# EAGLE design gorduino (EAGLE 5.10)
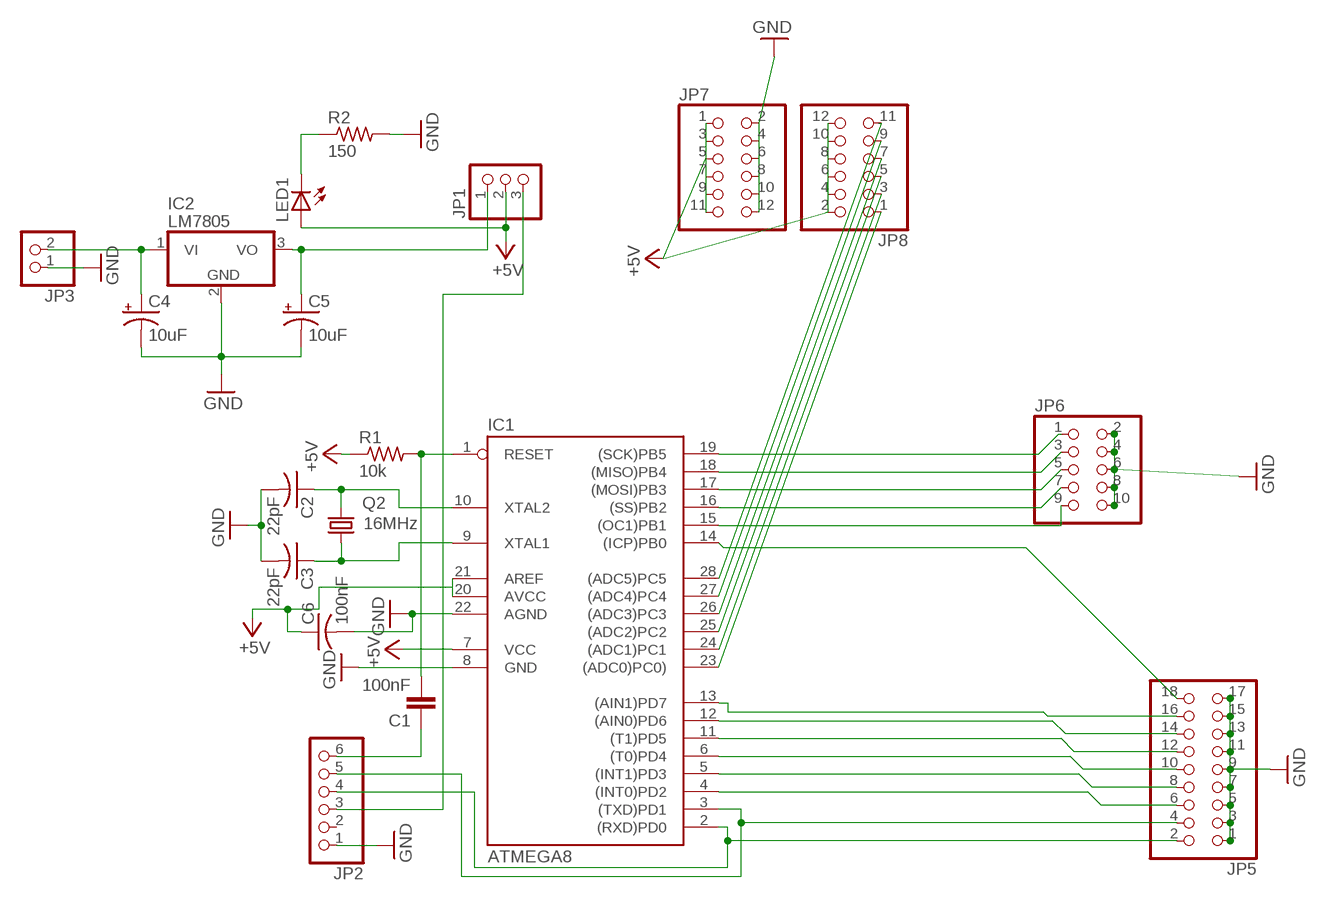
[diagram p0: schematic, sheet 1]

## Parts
C1  100nF  C2.5/2  [C2.5-2]
C2  22pF  C-US025-024X044  [C025-024X044]
C3  22pF  C-US025-024X044  [C025-024X044]
C4  10uF  CPOL-USE2.5-5  [E2,5-5]
C5  10uF  CPOL-USE2.5-5  [E2,5-5]
C6  100nF  C-US025-025X050  [C025-025X050]
IC1  ATMEGA8  AT90S4433P  [DIL28-3]
IC2  LM7805  7805TV  [TO220V]
JP1  PINHD-1X3  [1X03]
JP2  PINHD-1X6  [1X06]
JP3  PINHD-1X2  [1X02]
JP5  PINHD-2X9  [2X09]
JP6  PINHD-2X5  [2X05]
JP7  PINHD-2X6  [2X06]
JP8  PINHD-2X6  [2X06]
LED1  LED3MM  [LED3MM]
Q2  16MHz  CRYTALHC49S  [HC49/S]
R1  10k  R-US_0207/10  [0207/10]
R2  150  R-US_0207/10  [0207/10]

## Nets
+5V [usbvcc]: C6.1 IC1.7(VCC) IC1.20(AVCC) IC1.21(AREF) JP1.2 JP7.1 JP7.3 JP7.5 JP7.7 JP7.9 JP7.11 JP8.2 JP8.4 JP8.6 JP8.8 JP8.10 JP8.12 LED1.A R1.1
N$1: C4.+ IC2.1(VI) JP3.2
N$2 [usbvcc]: C5.+ IC2.3(VO) JP1.1
N$3: LED1.K(C) R2.1
N$4: C1.1 JP2.6
N$5: IC1.2((RXD)PD0) JP2.4 JP5.2
N$6: C3.1 IC1.9(XTAL1) Q2.1
N$7: C2.1 IC1.10(XTAL2) Q2.2
N$8: IC1.3((TXD)PD1) JP2.5 JP5.4
N$9: JP1.3 JP2.3
N$10: IC1.24((ADC1)PC1) JP8.3
N$11: IC1.23((ADC0)PC0)) JP8.1
N$12: IC1.25((ADC2)PC2) JP8.5
N$13: IC1.26((ADC3)PC3) JP8.7
N$14: IC1.27((ADC4)PC4) JP8.9
N$15: IC1.28((ADC5)PC5) JP8.11
N$16: IC1.13((AIN1)PD7) JP5.16
N$17: IC1.15((OC1)PB1) JP6.9
N$18: IC1.14((ICP)PB0) JP5.18
N$19: IC1.16((SS)PB2) JP6.7
N$20: IC1.4((INT0)PD2) JP5.6
N$21: IC1.5((INT1)PD3) JP5.8
N$22: IC1.6((T0)PD4) JP5.10
N$23: IC1.11((T1)PD5) JP5.12
N$24: IC1.12((AIN0)PD6) JP5.14
N$25: C2.2 C3.2 C4.- C5.- C6.2 IC1.8(GND) IC1.22(AGND) IC2.2(GND) JP2.1 JP3.1 JP5.1 JP5.3 JP5.5 JP5.7 JP5.9 JP5.11 JP5.13 JP5.15 JP5.17 JP6.2 JP6.4 JP6.6 JP6.8 JP6.10 JP7.2 JP7.4 JP7.6 JP7.8 JP7.10 JP7.12 R2.2 ; supply symbol labelled GND
N$28: IC1.17((MOSI)PB3) JP6.5
N$30: IC1.18((MISO)PB4) JP6.3
N$31: IC1.19((SCK)PB5) JP6.1
RESET: C1.2 IC1.1(RESET) R1.2
Unconnected: JP2.2

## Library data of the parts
C1 = capacitor-wima:C: CAPACITOR
C2 C3 C6 = resistor:C-US: CAPACITOR, American symbol
C4 C5 = resistor:CPOL-US: POLARIZED CAPACITOR, American symbol
IC1 = atmel:AT90S4433: MICROCONTROLLER 4 Kbytes FLASH 128 bytes SRAM 256 bytes EEPROM UART 6-channel 10 bit ADC
IC2 = linear:78*: Positive VOLTAGE REGULATOR Source: http://cache.national.com/ds/LM/LM78L05.pdf http://www.fairchildsemi.com/ds/LM/LM7805.pdf
JP1 = pinhead:PINHD-1X3: PIN HEADER
JP2 = pinhead:PINHD-1X6: PIN HEADER
JP3 = pinhead:PINHD-1X2: PIN HEADER
JP5 = pinhead:PINHD-2X9: PIN HEADER
JP6 = pinhead:PINHD-2X5: PIN HEADER
JP7 JP8 = pinhead:PINHD-2X6: PIN HEADER
LED1 = led:LED: LED
Q2 = crystal:CRYTAL: CRYSTAL
R1 R2 = resistor:R-US_: RESISTOR, American symbol

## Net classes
0 default: width 0.254 mm, clearance 0.254 mm
1 power: width 0.61 mm, drill 0.711 mm, clearance 0.33 mm
2 gnd: width 0.305 mm, drill 0.711 mm, clearance 0.254 mm
3 usbvcc: width 0.508 mm, drill 0.711 mm, clearance 0.254 mm
4 aref: width 0.406 mm

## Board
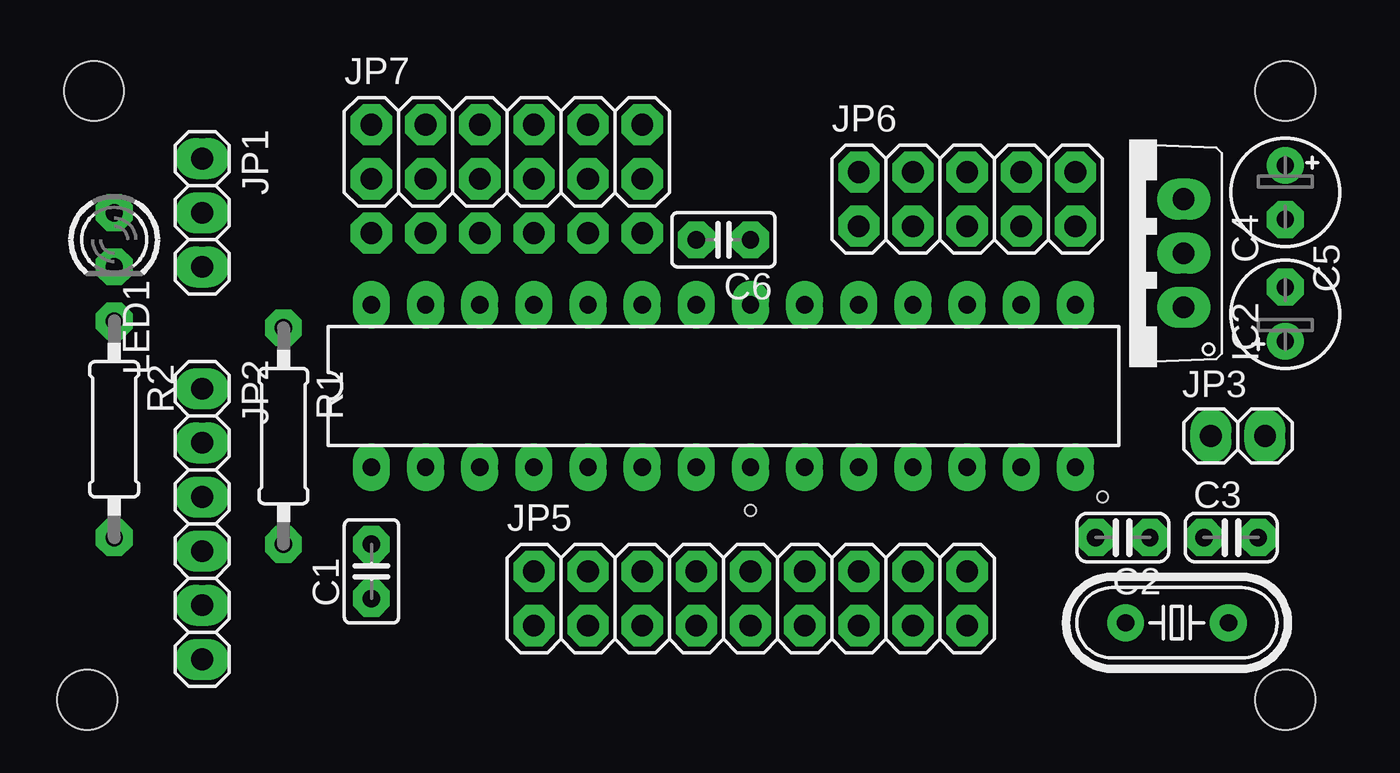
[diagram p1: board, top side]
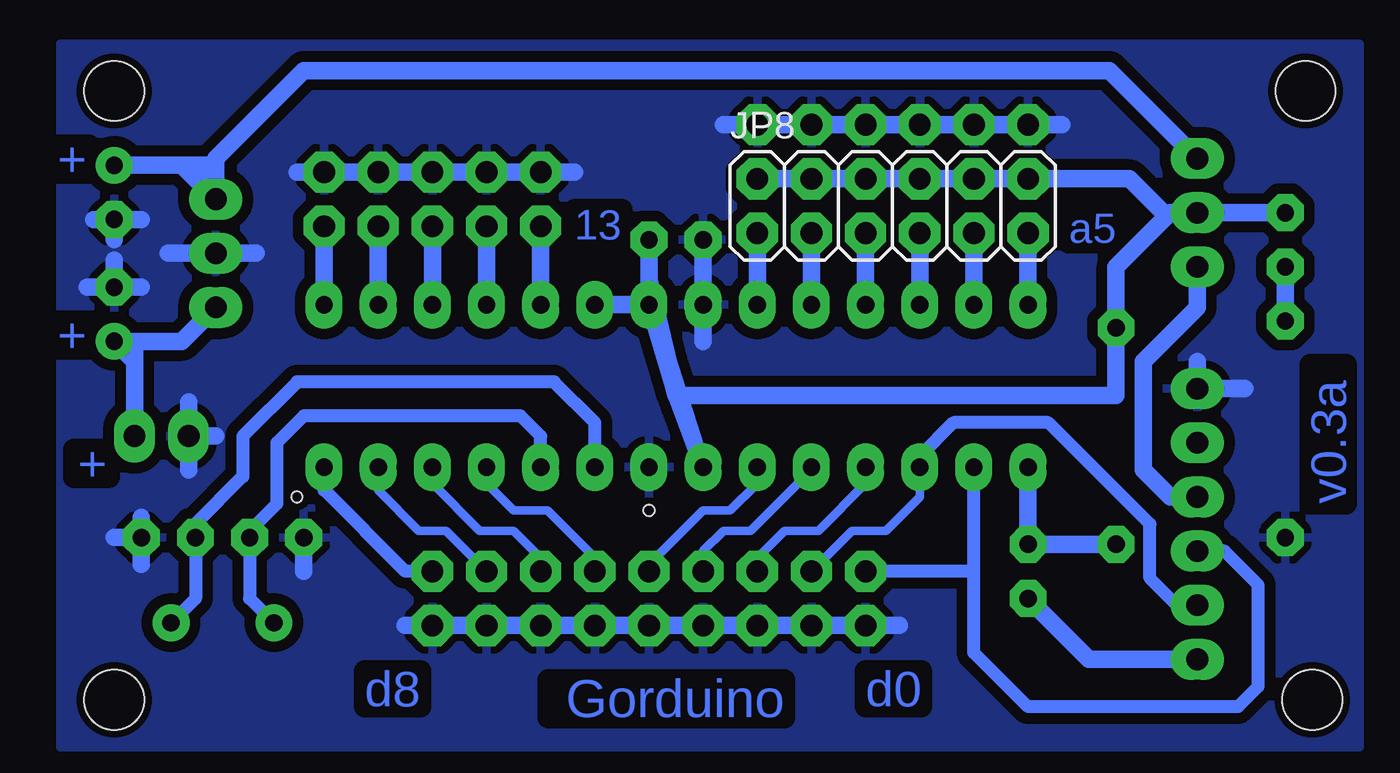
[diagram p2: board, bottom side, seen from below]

No outline drawn. Coordinates in mm, seen from the top.
Copper layers (1*16): Top 0.035mm / dielectric 1.5mm / Bottom 0.035mm
Design rules "default *": minimum track width 26mil, minimum drill 8mil, track to track 20mil, track to pad 24mil, pad to pad 24mil, via to via 24mil, smd to smd 24mil, copper to edge 14mil, drill to drill 14mil, minimum pad ring 18mil, minimum via ring 16mil, stop-mask expansion 4mil, vias tented up to drill 0mil, thermal gap 14mil
Holes 2.8 mm at 2.86,31.11 58.74,31.11 2.54,2.54 58.74,2.54
Holes 0.5 mm at 33.66,11.43 50.16,12.06

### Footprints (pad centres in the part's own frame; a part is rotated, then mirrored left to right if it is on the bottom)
C2.5-2 = drill 0.813 pad 1.6 octagon: 1 -1.27,0; 2 1.27,0
C025-024X044 = drill 0.813 octagon: 1 -1.27,0; 2 1.27,0
E2,5-5 = drill 0.813 pad 1.6 round: + -1.27,0 | drill 0.813 pad 1.6 octagon: - 1.27,0
C025-025X050 = drill 0.813 octagon: 1 -1.27,0; 2 1.27,0
DIL28-3 = drill 0.813 long: 1 -16.51,-3.81; 2 -13.97,-3.81; 3 -11.43,-3.81; 4 -8.89,-3.81; 5 -6.35,-3.81; 6 -3.81,-3.81; 7 -1.27,-3.81; 8 1.27,-3.81; 9 3.81,-3.81; 10 6.35,-3.81; 11 8.89,-3.81; 12 11.43,-3.81; 13 13.97,-3.81; 14 16.51,-3.81; 15 16.51,3.81; 16 13.97,3.81; 17 11.43,3.81; 18 8.89,3.81; 19 6.35,3.81; 20 3.81,3.81; 21 1.27,3.81; 22 -1.27,3.81; 23 -3.81,3.81; 24 -6.35,3.81; 25 -8.89,3.81; 26 -11.43,3.81; 27 -13.97,3.81; 28 -16.51,3.81
TO220V = drill 1.016 long: 1 -2.54,-2.54; 2 0,-2.54; 3 2.54,-2.54
1X03 = drill 1.016 long: 1 -2.54,0; 2 0,0; 3 2.54,0
1X06 = drill 1.016 long: 1 -6.35,0; 2 -3.81,0; 3 -1.27,0; 4 1.27,0; 5 3.81,0; 6 6.35,0
1X02 = drill 1.016 long: 1 -1.27,0; 2 1.27,0
2X09 = drill 1.016 octagon: 1 -10.16,-1.27; 2 -10.16,1.27; 3 -7.62,-1.27; 4 -7.62,1.27; 5 -5.08,-1.27; 6 -5.08,1.27; 7 -2.54,-1.27; 8 -2.54,1.27; 9 0,-1.27; 10 0,1.27; 11 2.54,-1.27; 12 2.54,1.27; 13 5.08,-1.27; 14 5.08,1.27; 15 7.62,-1.27; 16 7.62,1.27; 17 10.16,-1.27; 18 10.16,1.27
2X05 = drill 1.016 octagon: 1 -5.08,-1.27; 2 -5.08,1.27; 3 -2.54,-1.27; 4 -2.54,1.27; 5 0,-1.27; 6 0,1.27; 7 2.54,-1.27; 8 2.54,1.27; 9 5.08,-1.27; 10 5.08,1.27
2X06 = drill 1.016 octagon: 1 -6.35,-1.27; 2 -6.35,1.27; 3 -3.81,-1.27; 4 -3.81,1.27; 5 -1.27,-1.27; 6 -1.27,1.27; 7 1.27,-1.27; 8 1.27,1.27; 9 3.81,-1.27; 10 3.81,1.27; 11 6.35,-1.27; 12 6.35,1.27
LED3MM = drill 0.813 octagon: A -1.27,0; K 1.27,0
HC49/S = drill 0.813 round: 1 -2.413,0; 2 2.413,0
0207/10 = drill 0.813 octagon: 1 -5.08,0; 2 5.08,0

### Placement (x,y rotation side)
C1  15.88,8.57 90 top
C2  51.12,10.16 180 top
C3  56.2,10.16 0 top
C4  58.74,20.64 90 top
C5  58.74,26.35 270 top
C6  32.38,24.13 180 top
IC1  32.38,17.27 0 top
IC2  51.44,23.5 90 top
JP1  7.94,25.4 270 top
JP2  7.94,10.79 270 top
JP3  56.52,14.92 0 top
JP5  33.66,7.3 0 top
JP6  43.81,26.04 0 top
JP7  22.23,28.26 0 top
JP8  22.23,25.72 0 bottom
LED1  3.81,24.13 270 top
Q2  53.66,6.16 180 top
R1  11.75,14.92 270 top
R2  3.81,15.24 270 top

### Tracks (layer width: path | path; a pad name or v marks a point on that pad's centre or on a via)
+5V
  Bottom 0.813: IC1.21 IC1.20 | 33.66,22.23 IC1.21 | 32.38,16.83 32.44,17 | 32.44,17 IC1.21 | 32.44,17 IC1.7 | 32.38,16.83 33.66,22.23 | 32.38,16.83 11.75,16.83 R1.1 11.75,22.86 9.37,25.24 | LED1.A JP1.2 9.21,25.4 9.37,25.24 | 33.66,22.23 C6.1 | JP8.12 JP8.10 JP8.8 JP8.6 JP8.4 JP8.2 JP8.12 | JP8.12 11.11,26.99 9.37,25.24
N$1
  Bottom 0.813: IC2.1 55.56,19.37 C4.+ 57.78,18.41 | JP3.2 57.78,17.78 57.78,18.41 | 57.78,18.41 57.78,19.05
N$2
  Bottom 0.813: JP1.1 12.06,32.07 49.85,32.07 53.98,27.94 53.98,27.62 | 53.98,27.62 IC2.3 55.56,27.62 C5.+ 54.29,27.62 | 53.98,27.62 54.29,27.62 | 54.29,27.62 54.29,27.3
N$3
  Bottom 0.813: R2.1 LED1.K
N$4
  Bottom 0.813: C1.1 13.02,4.45 JP2.6
N$5
  Bottom 0.61: JP2.4 6.67,9.53 5.08,7.94 5.08,3.17 6.03,2.22 15.88,2.22 18.41,4.76 18.41,8.57 | 18.41,8.57 IC1.2 | 18.41,8.57 JP5.2
N$6
  Bottom 0.61: Q2.1 54.93,7.3 C3.1 54.93,10.79 52.7,13.02 52.7,14.92 50.16,17.46 38.1,17.46 36.2,15.56 IC1.9
N$7
  Bottom 0.61: Q2.2 52.39,7.3 C2.1 52.39,10.48 51.12,11.75 51.12,14.61 49.85,15.88 39.69,15.88 38.73,14.92 IC1.10
N$8
  Bottom 0.406: IC1.3 20.95,12.06 22.54,10.48 24.13,10.48 JP5.4
  Bottom 0.61: JP2.5 8.89,6.99 10.16,8.26 10.16,10.79 14.92,15.56 19.37,15.56 20.95,13.97 IC1.3
N$9
  Bottom 0.813: JP1.3 7.94,20.95 10.48,18.41 10.48,13.34 9.21,12.06 JP2.3
N$10
  Bottom 0.813: IC1.24 JP8.3
N$11
  Bottom 0.813: IC1.23 JP8.1
N$12
  Bottom 0.813: IC1.25 JP8.5
N$13
  Bottom 0.813: IC1.26 JP8.7
N$14
  Bottom 0.813: IC1.27 JP8.9
N$15
  Bottom 0.813: IC1.28 JP8.11
N$16
  Bottom 0.406: JP5.16 43.18,10.48 44.45,10.48 46.35,12.38 IC1.13
N$17
  Bottom 0.813: IC1.15 JP6.9
N$18
  Bottom 0.61: IC1.14 48.9,12.38 45.09,8.57 JP5.18
N$19
  Bottom 0.813: IC1.16 JP6.7
N$20
  Bottom 0.406: IC1.4 23.5,12.7 25.72,10.48 27.3,10.48 28.57,9.21 JP5.6
N$21
  Bottom 0.406: IC1.5 26.04,13.34 28.89,10.48 30.16,10.48 31.11,9.53 JP5.8
N$22
  Bottom 0.406: JP5.10 33.66,8.89 31.11,11.43 29.84,11.43 28.57,12.7 IC1.6
N$23
  Bottom 0.406: JP5.12 36.2,9.21 38.42,11.43 40.01,11.43 41.27,12.7 IC1.11
N$24
  Bottom 0.406: IC1.12 43.81,12.7 41.59,10.48 40.01,10.48 38.73,9.21 JP5.14
N$25
  Bottom 0.813: 30.16,29.53 JP7.2 14.29,29.53 | 45.09,6.03 JP5.1 21.91,6.03 | 49.85,8.57 C2.2 | 56.2,23.5 IC2.2 52.07,23.5 | 50.16,27.3 JP6.2 37.15,27.3 | C3.2 58.74,10.16 | C3.2 57.47,11.11 | 57.47,8.89 C3.2 | C5.- 59.69,25.08 | 57.47,25.08 C5.- | C5.- 58.74,24.13 | C4.- 58.74,23.18 | C4.- 60.01,21.91 | 57.47,21.91 C4.- | JP3.1 55.24,16.51 | JP3.1 55.24,13.34 | JP3.1 53.98,14.92 | 31.11,19.37 C6.2 | 5.71,17.14 JP2.1 7.94,18.41
  pour Bottom: 61.28,0.32 0.32,0.32 0.32,33.34 61.28,33.34
N$26
  Bottom 0.813: 31.11,13.34 33.66,21.27
N$28
  Bottom 0.813: IC1.17 JP6.5
N$30
  Bottom 0.813: IC1.18 JP6.3
N$31
  Bottom 0.813: IC1.19 JP6.1
RESET
  Bottom 0.813: IC1.1 C1.2 R1.2

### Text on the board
Bottom: + | a5 | 13 | + | + | v0.3a | Gorduino | d0 | d8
